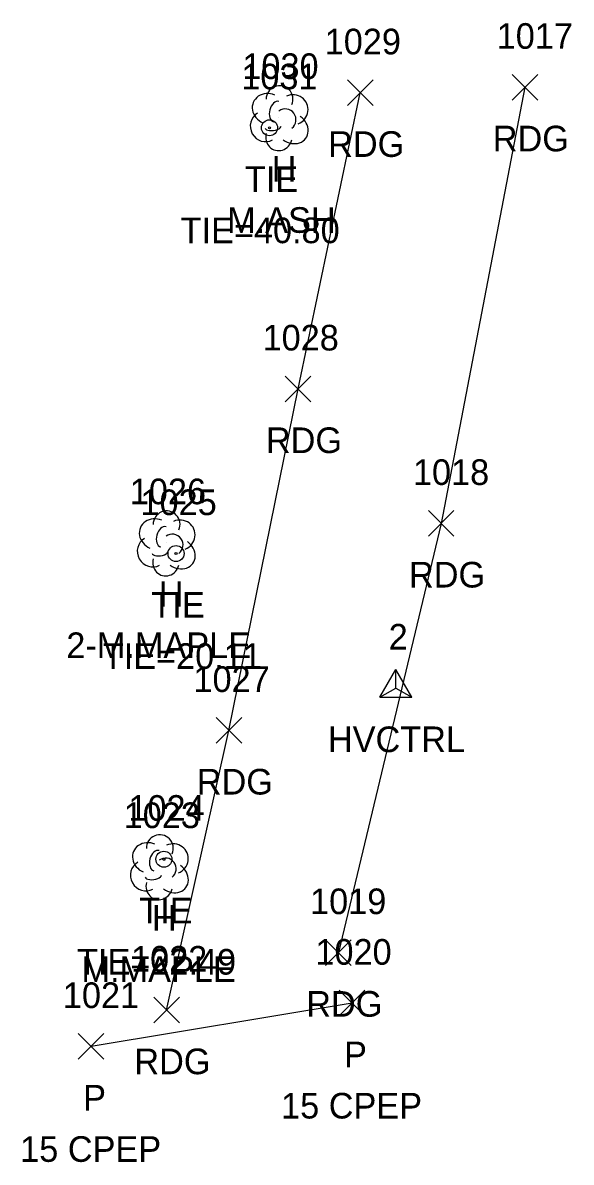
# Model space of a CAD drawing. Extents: x 1441651 to 1442140, y 243798 to 245625.
# Drawn here: x 1441952.5 to 1441995.3, y 244991 to 245079.8 of the extents above; entities that cross this region are included whole.
import ezdxf

# ---------------------------------------------------------------- set-up
doc = ezdxf.new("R2010")
doc.units = 0
for name, color, linetype in [('C_A', 7, 'Continuous'), ('C_C', 7, 'Continuous'), ('C_I', 7, 'Continuous'), ('CBP', 7, 'Continuous'), ('CPSM', 7, 'Continuous'), ('D_A', 7, 'Continuous'), ('D_C', 7, 'Continuous'), ('D_I', 7, 'Continuous'), ('D_TIC', 7, 'Continuous'), ('DCP', 7, 'Continuous'), ('L_A', 7, 'Continuous'), ('L_C', 7, 'Continuous'), ('L_I', 7, 'Continuous'), ('LTD', 7, 'Continuous'), ('P_A', 7, 'Continuous'), ('P_I', 7, 'Continuous'), ('P_TIC', 7, 'Continuous'), ('PEU', 7, 'Continuous')]:
    doc.layers.add(name, color=color, linetype=linetype)

msp = doc.modelspace()

# ---------------------------------------------------------------- linework, layer by layer
at = {"layer": 'CBP'}
for centre, radius in [((1441971.731, 245071.65), 0.625), ((1441971.731, 245071.65), 0.0833), ((1441964.436, 245038.438), 0.625), ((1441964.436, 245038.438), 0.0833), ((1441963.492, 245014.59), 0.625), ((1441963.492, 245014.59), 0.0833)]:
    msp.add_circle(centre, radius, dxfattribs=at)
at = {"layer": 'CPSM'}
for p, q in [((1441980.346, 245027.225), (1441981.596, 245029.39)), ((1441982.846, 245027.225), (1441981.596, 245029.39)), ((1441981.596, 245027.946), (1441981.596, 245029.39)), ((1441980.346, 245027.225), (1441981.596, 245027.946)), ((1441981.596, 245027.946), (1441981.596, 245027.946)), ((1441981.596, 245027.946), (1441982.846, 245027.225)), ((1441980.346, 245027.225), (1441982.846, 245027.225))]:
    msp.add_line(p, q, dxfattribs=at)
at = {"layer": 'D_TIC'}
for points in [[(1441977.171, 245002.365), (1441979.171, 245004.365)], [(1441979.171, 245002.365), (1441977.171, 245004.365)], [(1441956.811, 244998.984), (1441958.811, 245000.984)], [(1441958.811, 244998.984), (1441956.811, 245000.984)]]:
    msp.add_lwpolyline(points, dxfattribs=at)
at = {"layer": 'DCP'}
msp.add_lwpolyline([(1441978.171, 245003.365), (1441957.811, 244999.984)], dxfattribs=at)
at = {"layer": 'LTD'}
for p, q in [((1441972.47, 245072.457), (1441972.47, 245072.457)), ((1441972.47, 245072.457), (1441972.47, 245072.457)), ((1441963.656, 245039.283), (1441963.656, 245039.283)), ((1441963.656, 245039.283), (1441963.656, 245039.283)), ((1441963.124, 245014.02), (1441963.124, 245014.02)), ((1441963.124, 245014.02), (1441963.124, 245014.02))]:
    msp.add_line(p, q, dxfattribs=at)
for centre in [(1441972.516, 245073.891), (1441963.702, 245040.717), (1441963.171, 245015.454)]:
    msp.add_arc(centre, 1.047, 335.52715, 180.95627, dxfattribs=at)
for centre, major_axis, ratio, start_param, end_param in [((1441971.678, 245073.124), (1.21, -0.512), 0.895232, 1.570796, 4.712389), ((1441972.261, 245072.916), (-0.208, -0.792), 0.645439, 3.141593, 6.283185), ((1441973.511, 245073.041), (-1.141, -0.483), 0.949671, 1.570796, 4.712389), ((1441972.97, 245072.291), (-0.5, 0.667), 0.989748, 3.141593, 6.283185), ((1441971.386, 245071.749), (0.584, -1.042), 0.959034, 3.141593, 6.283185), ((1441973.47, 245071.624), (-1.09, 0.792), 0.841452, 1.570796, 4.712389), ((1441972.47, 245070.957), (0.265, 1.061), 0.942809, 1.570796, 4.712389), ((1441972.011, 245071.707), (-0.625, -0.083), 0.423636, 0, 3.141593), ((1441962.864, 245039.949), (1.21, -0.512), 0.895232, 1.570796, 4.712389), ((1441964.697, 245039.866), (-1.141, -0.483), 0.949671, 1.570796, 4.712389), ((1441963.447, 245039.741), (-0.208, -0.792), 0.645439, 3.141593, 6.283185), ((1441964.156, 245039.116), (-0.5, 0.667), 0.989748, 3.141593, 6.283185), ((1441962.572, 245038.574), (0.584, -1.042), 0.959034, 3.141593, 6.283185), ((1441964.656, 245038.449), (-1.09, 0.792), 0.841452, 1.570796, 4.712389), ((1441963.197, 245038.533), (-0.625, -0.083), 0.423636, 0, 3.141593), ((1441963.656, 245037.783), (0.265, 1.061), 0.942809, 1.570796, 4.712389), ((1441962.332, 245014.686), (1.21, -0.512), 0.895232, 1.570796, 4.712389), ((1441964.165, 245014.603), (-1.141, -0.483), 0.949671, 1.570796, 4.712389), ((1441962.915, 245014.478), (-0.208, -0.792), 0.645439, 3.141593, 6.283185), ((1441962.041, 245013.311), (0.584, -1.042), 0.959034, 3.141593, 6.283185), ((1441963.624, 245013.853), (-0.5, 0.667), 0.989748, 3.141593, 6.283185), ((1441962.666, 245013.27), (-0.625, -0.083), 0.423636, 0, 3.141593), ((1441964.124, 245013.187), (-1.09, 0.792), 0.841452, 1.570796, 4.712389), ((1441963.124, 245012.52), (0.265, 1.061), 0.942809, 1.570796, 4.712389)]:
    msp.add_ellipse(centre, major_axis=major_axis, ratio=ratio, start_param=start_param, end_param=end_param, dxfattribs=at)
at = {"layer": 'P_TIC'}
for points in [[(1441990.663, 245073.813), (1441992.663, 245075.813)], [(1441992.663, 245073.813), (1441990.663, 245075.813)], [(1441977.817, 245073.381), (1441979.817, 245075.381)], [(1441979.817, 245073.381), (1441977.817, 245075.381)], [(1441972.961, 245050.278), (1441974.961, 245052.278)], [(1441974.961, 245050.278), (1441972.961, 245052.278)], [(1441984.127, 245039.789), (1441986.127, 245041.789)], [(1441986.127, 245039.789), (1441984.127, 245041.789)], [(1441967.57, 245023.639), (1441969.57, 245025.639)], [(1441969.57, 245023.639), (1441967.57, 245025.639)], [(1441976.109, 245006.308), (1441978.109, 245008.308)], [(1441978.109, 245006.308), (1441976.109, 245008.308)], [(1441962.696, 245001.822), (1441964.696, 245003.822)], [(1441964.696, 245001.822), (1441962.696, 245003.822)]]:
    msp.add_lwpolyline(points, dxfattribs=at)
at = {"layer": 'PEU'}
for points in [[(1441991.663, 245074.813), (1441985.127, 245040.789), (1441977.109, 245007.308)], [(1441963.696, 245002.822), (1441968.57, 245024.639), (1441973.961, 245051.278), (1441978.817, 245074.381)]]:
    msp.add_lwpolyline(points, dxfattribs=at)

# ---------------------------------------------------------------- texts
at = {"layer": 'C_A'}
for s, p in [('TIE', (1441969.809, 245066.65)), ('TIE', (1441962.514, 245033.438)), ('HVCTRL', (1441976.289, 245022.946)), ('TIE', (1441961.571, 245009.59))]:
    msp.add_text(s, height=2, dxfattribs=at).set_placement(p)
at = {"layer": 'C_C'}
for s, p in [('TIE=40.80', (1441964.794, 245062.65)), ('TIE=20.11', (1441958.719, 245029.438)), ('TIE=22.49', (1441956.712, 245005.59))]:
    msp.add_text(s, height=2, dxfattribs=at).set_placement(p)
at = {"layer": 'C_I'}
for s, p in [('1031', (1441969.526, 245074.65)), ('1025', (1441961.664, 245041.438)), ('2', (1441981.029, 245030.946)), ('1024', (1441960.72, 245017.59))]:
    msp.add_text(s, height=2, dxfattribs=at).set_placement(p)
at = {"layer": 'D_A'}
for p in [(1441977.549, 244998.365), (1441957.189, 244994.984)]:
    msp.add_text('P', height=2, dxfattribs=at).set_placement(p)
at = {"layer": 'D_C'}
for p in [(1441972.635, 244994.365), (1441952.276, 244990.984)]:
    msp.add_text('15 CPEP', height=2, dxfattribs=at).set_placement(p)
at = {"layer": 'D_I'}
for s, p in [('1020', (1441975.313, 245006.365)), ('1021', (1441955.607, 245002.984))]:
    msp.add_text(s, height=2, dxfattribs=at).set_placement(p)
at = {"layer": 'L_A'}
for p in [(1441971.903, 245067.457), (1441963.089, 245034.283), (1441962.557, 245009.02)]:
    msp.add_text('H', height=2, dxfattribs=at).set_placement(p)
at = {"layer": 'L_C'}
for s, p in [('M.ASH', (1441968.422, 245063.457)), ('2-M.MAPLE', (1441955.876, 245030.283)), ('M.MAPLE', (1441957.061, 245005.02))]:
    msp.add_text(s, height=2, dxfattribs=at).set_placement(p)
at = {"layer": 'L_I'}
for s, p in [('1030', (1441969.611, 245075.457)), ('1026', (1441960.829, 245042.283)), ('1023', (1441960.352, 245017.02))]:
    msp.add_text(s, height=2, dxfattribs=at).set_placement(p)
at = {"layer": 'P_A'}
for p in [(1441976.306, 245069.381), (1441989.151, 245069.813), (1441971.449, 245046.278), (1441982.615, 245035.789), (1441966.058, 245019.639), (1441974.597, 245002.308), (1441961.184, 244997.822)]:
    msp.add_text('RDG', height=2, dxfattribs=at).set_placement(p)
at = {"layer": 'P_I'}
for s, p in [('1029', (1441976.038, 245077.381)), ('1017', (1441989.458, 245077.813)), ('1028', (1441971.189, 245054.278)), ('1018', (1441982.922, 245043.789)), ('1027', (1441965.798, 245027.639)), ('1019', (1441974.896, 245010.308)), ('1022', (1441960.925, 245005.822))]:
    msp.add_text(s, height=2, dxfattribs=at).set_placement(p)

doc.saveas('drawing.dxf')
